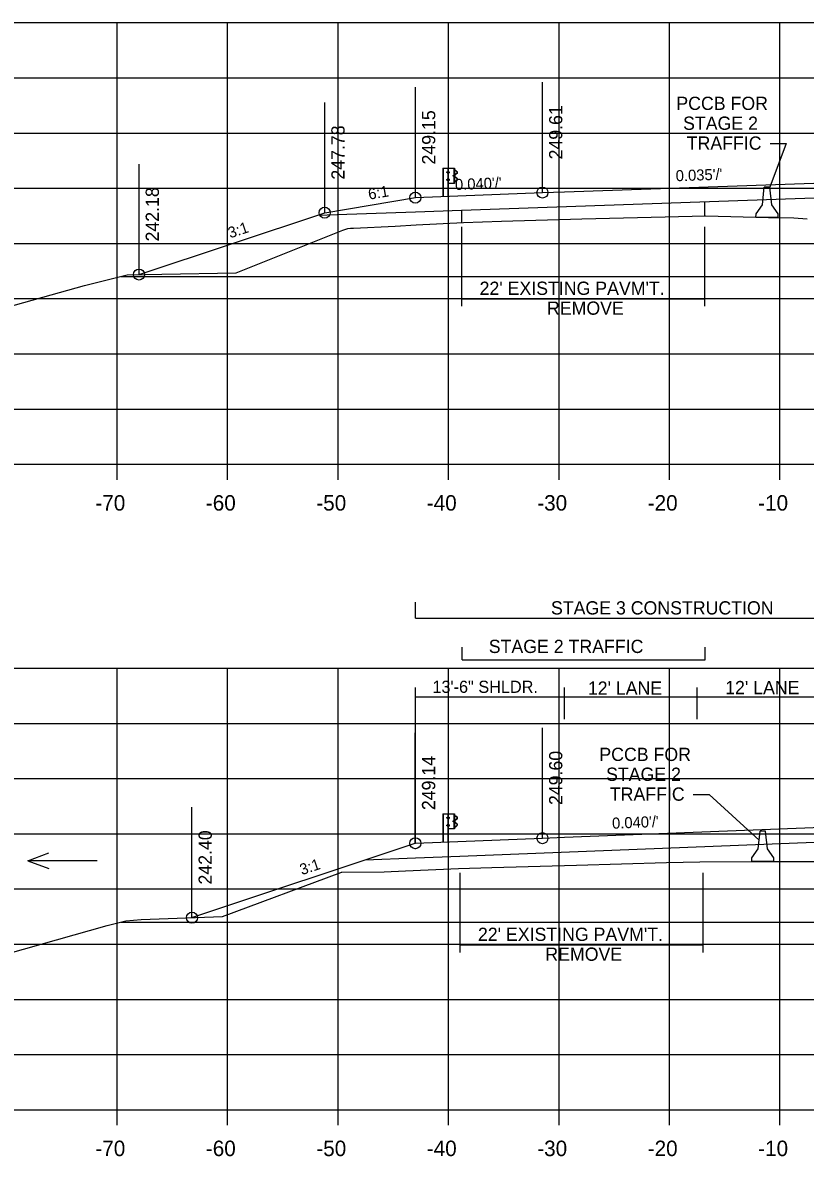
# Model space of a CAD drawing. Extents: x 1342547 to 1344156, y -1532351 to -1517216.
# Drawn here: x 1342624.3 to 1342695.2, y -1528712.1 to -1528609.4 of the extents above; entities that cross this region are included whole.
import ezdxf

# ---------------------------------------------------------------- set-up
doc = ezdxf.new("R2010")
doc.units = 0
for name, color, linetype in [('R_Alt Surface', 7, 'Continuous'), ('R_Axis', 7, 'Continuous'), ('R_Axis Annot', 7, 'Continuous'), ('R_Draft', 7, 'Continuous'), ('R_Exist Surface', 7, 'Continuous'), ('R_Fin Surface', 7, 'Continuous'), ('R_Grid', 7, 'Continuous'), ('R_MOT', 7, 'Continuous'), ('R_No Plot', 7, 'Continuous'), ('R_Water', 7, 'Continuous'), ('R_Xsect Elev', 7, 'Continuous'), ('R_Xsect Slope', 7, 'Continuous')]:
    doc.layers.add(name, color=color, linetype=linetype)

msp = doc.modelspace()

# ---------------------------------------------------------------- linework, layer by layer
at = {"layer": 'R_Alt Surface'}
for points in [[(1342664.04, -1528626.38), (1342702.87, -1528625.03)], [(1342651.02, -1528626.83), (1342659.87, -1528626.53)], [(1342659.87, -1528626.53), (1342664.04, -1528626.38)], [(1342663.89, -1528684.9), (1342702.87, -1528683.35)], [(1342655.33, -1528685.24), (1342659.87, -1528685.06)], [(1342659.87, -1528685.06), (1342663.89, -1528684.9)]]:
    msp.add_lwpolyline(points, dxfattribs=at)
at = {"layer": 'R_Axis'}
for p, q in [((1342562.87, -1528649.4), (1342842.87, -1528649.4)), ((1342632.87, -1528650.8), (1342632.87, -1528649.4)), ((1342642.87, -1528650.8), (1342642.87, -1528649.4)), ((1342652.87, -1528650.8), (1342652.87, -1528649.4)), ((1342662.87, -1528650.8), (1342662.87, -1528649.4)), ((1342672.87, -1528650.8), (1342672.87, -1528649.4)), ((1342682.87, -1528650.8), (1342682.87, -1528649.4)), ((1342692.87, -1528650.8), (1342692.87, -1528649.4)), ((1342562.87, -1528707.87), (1342842.87, -1528707.87)), ((1342632.87, -1528709.27), (1342632.87, -1528707.87)), ((1342642.87, -1528709.27), (1342642.87, -1528707.87)), ((1342652.87, -1528709.27), (1342652.87, -1528707.87)), ((1342662.87, -1528709.27), (1342662.87, -1528707.87)), ((1342672.87, -1528709.27), (1342672.87, -1528707.87)), ((1342682.87, -1528709.27), (1342682.87, -1528707.87)), ((1342692.87, -1528709.27), (1342692.87, -1528707.87))]:
    msp.add_line(p, q, dxfattribs=at)
at = {"layer": 'R_Draft'}
for p, q in [((1342662.35, -1528622.59), (1342662.35, -1528625.11)), ((1342662.38, -1528622.59), (1342662.38, -1528625.11)), ((1342662.75, -1528623), (1342662.75, -1528622.91)), ((1342662.81, -1528622.89), (1342662.76, -1528622.89)), ((1342662.81, -1528622.92), (1342662.76, -1528622.92)), ((1342662.81, -1528622.98), (1342662.76, -1528622.98)), ((1342662.81, -1528622.98), (1342662.76, -1528622.98)), ((1342662.81, -1528623.02), (1342662.76, -1528623.02)), ((1342662.88, -1528622.59), (1342662.81, -1528622.59)), ((1342662.81, -1528623.02), (1342662.81, -1528622.89)), ((1342662.84, -1528625.11), (1342662.84, -1528622.59)), ((1342662.88, -1528622.59), (1342662.87, -1528622.59)), ((1342662.93, -1528622.96), (1342662.87, -1528622.96)), ((1342662.88, -1528622.9), (1342662.93, -1528622.9)), ((1342662.88, -1528623.02), (1342662.93, -1528623.02)), ((1342662.93, -1528622.9), (1342662.93, -1528623.02)), ((1342663.37, -1528623.96), (1342663.37, -1528622.6)), ((1342663.52, -1528622.8), (1342663.41, -1528622.74)), ((1342663.51, -1528622.82), (1342663.41, -1528622.77)), ((1342663.46, -1528623.14), (1342663.63, -1528623.03)), ((1342663.47, -1528623.16), (1342663.65, -1528623.05)), ((1342663.64, -1528622.92), (1342663.51, -1528622.82)), ((1342663.65, -1528622.91), (1342663.52, -1528622.8)), ((1342662.74, -1528623.69), (1342662.74, -1528623.59)), ((1342662.8, -1528623.58), (1342662.75, -1528623.58)), ((1342662.8, -1528623.61), (1342662.75, -1528623.61)), ((1342662.8, -1528623.67), (1342662.75, -1528623.67)), ((1342662.8, -1528623.67), (1342662.75, -1528623.67)), ((1342662.8, -1528623.7), (1342662.75, -1528623.7)), ((1342662.8, -1528623.7), (1342662.8, -1528623.58)), ((1342662.87, -1528623.96), (1342662.84, -1528623.96)), ((1342662.93, -1528623.64), (1342662.87, -1528623.64)), ((1342662.93, -1528623.58), (1342662.88, -1528623.58)), ((1342662.93, -1528623.7), (1342662.88, -1528623.7)), ((1342662.93, -1528623.7), (1342662.93, -1528623.58)), ((1342663.36, -1528623.21), (1342663.31, -1528623.21)), ((1342663.31, -1528623.32), (1342663.31, -1528623.23)), ((1342663.36, -1528623.24), (1342663.31, -1528623.24)), ((1342663.36, -1528623.31), (1342663.31, -1528623.31)), ((1342663.36, -1528623.34), (1342663.31, -1528623.34)), ((1342663.36, -1528623.31), (1342663.32, -1528623.31)), ((1342663.36, -1528623.34), (1342663.36, -1528623.21)), ((1342663.4, -1528623.79), (1342663.51, -1528623.74)), ((1342663.41, -1528623.34), (1342663.42, -1528623.2)), ((1342663.41, -1528623.81), (1342663.52, -1528623.75)), ((1342663.44, -1528623.34), (1342663.44, -1528623.2)), ((1342663.61, -1528623.51), (1342663.46, -1528623.41)), ((1342663.62, -1528623.49), (1342663.47, -1528623.39)), ((1342663.51, -1528623.74), (1342663.64, -1528623.63)), ((1342663.52, -1528623.75), (1342663.65, -1528623.65)), ((1342686.04, -1528625.62), (1342686.04, -1528626.91)), ((1342664.04, -1528626.38), (1342664.04, -1528627.49)), ((1342664.04, -1528627.9), (1342664.04, -1528635.09)), ((1342686.05, -1528627.9), (1342686.05, -1528635.09)), ((1342664.04, -1528634.42), (1342686.05, -1528634.42)), ((1342659.87, -1528663.33), (1342659.87, -1528661.9)), ((1342659.87, -1528663.33), (1342702.78, -1528663.33)), ((1342664.11, -1528667.13), (1342664.11, -1528665.98)), ((1342686.11, -1528667.13), (1342686.11, -1528665.98)), ((1342664.11, -1528667.13), (1342686.11, -1528667.13)), ((1342662.35, -1528681.06), (1342662.35, -1528683.58)), ((1342662.38, -1528681.06), (1342662.38, -1528683.58)), ((1342662.75, -1528681.47), (1342662.75, -1528681.38)), ((1342662.81, -1528681.36), (1342662.76, -1528681.36)), ((1342662.81, -1528681.39), (1342662.76, -1528681.39)), ((1342662.81, -1528681.46), (1342662.76, -1528681.46)), ((1342662.81, -1528681.46), (1342662.76, -1528681.46)), ((1342662.81, -1528681.49), (1342662.76, -1528681.49)), ((1342662.88, -1528681.06), (1342662.81, -1528681.06)), ((1342662.81, -1528681.49), (1342662.81, -1528681.36)), ((1342662.84, -1528683.58), (1342662.84, -1528681.06)), ((1342662.88, -1528681.06), (1342662.87, -1528681.06)), ((1342662.93, -1528681.43), (1342662.87, -1528681.43)), ((1342662.88, -1528681.37), (1342662.93, -1528681.37)), ((1342662.88, -1528681.49), (1342662.93, -1528681.49)), ((1342662.93, -1528681.37), (1342662.93, -1528681.49)), ((1342663.36, -1528681.68), (1342663.31, -1528681.68)), ((1342663.36, -1528681.81), (1342663.36, -1528681.68)), ((1342663.37, -1528682.43), (1342663.37, -1528681.07)), ((1342663.52, -1528681.27), (1342663.41, -1528681.21)), ((1342663.51, -1528681.29), (1342663.41, -1528681.24)), ((1342663.41, -1528681.81), (1342663.42, -1528681.68)), ((1342663.44, -1528681.81), (1342663.44, -1528681.68)), ((1342663.46, -1528681.61), (1342663.63, -1528681.5)), ((1342663.47, -1528681.63), (1342663.65, -1528681.52)), ((1342663.64, -1528681.39), (1342663.51, -1528681.29)), ((1342663.65, -1528681.38), (1342663.52, -1528681.27)), ((1342662.74, -1528682.16), (1342662.74, -1528682.07)), ((1342662.8, -1528682.05), (1342662.75, -1528682.05)), ((1342662.8, -1528682.08), (1342662.75, -1528682.08)), ((1342662.8, -1528682.15), (1342662.75, -1528682.15)), ((1342662.8, -1528682.15), (1342662.75, -1528682.15)), ((1342662.8, -1528682.18), (1342662.75, -1528682.18)), ((1342662.8, -1528682.18), (1342662.8, -1528682.05)), ((1342662.87, -1528682.43), (1342662.84, -1528682.43)), ((1342662.93, -1528682.11), (1342662.87, -1528682.11)), ((1342662.93, -1528682.05), (1342662.88, -1528682.05)), ((1342662.93, -1528682.18), (1342662.88, -1528682.18)), ((1342662.93, -1528682.18), (1342662.93, -1528682.05)), ((1342663.31, -1528681.79), (1342663.31, -1528681.7)), ((1342663.36, -1528681.71), (1342663.31, -1528681.71)), ((1342663.36, -1528681.78), (1342663.31, -1528681.78)), ((1342663.36, -1528681.81), (1342663.31, -1528681.81)), ((1342663.36, -1528681.78), (1342663.32, -1528681.78)), ((1342663.4, -1528682.26), (1342663.51, -1528682.21)), ((1342663.41, -1528682.28), (1342663.52, -1528682.23)), ((1342663.61, -1528681.98), (1342663.46, -1528681.88)), ((1342663.62, -1528681.96), (1342663.47, -1528681.86)), ((1342663.51, -1528682.21), (1342663.64, -1528682.1)), ((1342663.52, -1528682.23), (1342663.65, -1528682.12)), ((1342663.89, -1528686.42), (1342663.89, -1528693.62)), ((1342685.89, -1528686.42), (1342685.89, -1528693.62)), ((1342663.89, -1528692.94), (1342685.89, -1528692.94))]:
    msp.add_line(p, q, dxfattribs=at)
for points in [[(1342693.42, -1528620.34), (1342691.95, -1528624.31)], [(1342691.97, -1528620.34), (1342693.42, -1528620.34)], [(1342662.35, -1528622.59), (1342662.81, -1528622.59), (1342662.8, -1528625.11)], [(1342685.01, -1528679.31), (1342686.45, -1528679.31)], [(1342686.45, -1528679.31), (1342690.99, -1528683.44)], [(1342662.35, -1528681.06), (1342662.81, -1528681.06), (1342662.8, -1528683.58)]]:
    msp.add_lwpolyline(points, dxfattribs=at)
for points in [[(1342662.75, -1528622.92), (1342662.75, -1528622.98), (1342662.72, -1528622.98), (1342662.72, -1528622.92)], [(1342662.8, -1528622.87), (1342662.8, -1528623.04), (1342662.81, -1528623.04), (1342662.81, -1528622.87)], [(1342663.4, -1528622.59), (1342663.4, -1528623.96), (1342662.87, -1528623.96), (1342662.88, -1528622.59)], [(1342662.93, -1528622.9), (1342662.93, -1528623.02), (1342662.88, -1528623.02), (1342662.88, -1528622.9)], [(1342662.74, -1528623.61), (1342662.74, -1528623.67), (1342662.71, -1528623.67), (1342662.71, -1528623.61)], [(1342662.79, -1528623.56), (1342662.79, -1528623.73), (1342662.8, -1528623.73), (1342662.8, -1528623.56)], [(1342662.93, -1528623.58), (1342662.93, -1528623.7), (1342662.88, -1528623.7), (1342662.88, -1528623.58)], [(1342663.3, -1528623.24), (1342663.3, -1528623.31), (1342663.28, -1528623.31), (1342663.28, -1528623.24)], [(1342663.36, -1528623.19), (1342663.36, -1528623.36), (1342663.37, -1528623.36), (1342663.37, -1528623.19)], [(1342662.75, -1528681.39), (1342662.75, -1528681.45), (1342662.72, -1528681.45), (1342662.72, -1528681.39)], [(1342662.8, -1528681.34), (1342662.8, -1528681.51), (1342662.81, -1528681.51), (1342662.81, -1528681.34)], [(1342663.4, -1528681.06), (1342663.4, -1528682.43), (1342662.87, -1528682.43), (1342662.88, -1528681.06)], [(1342662.93, -1528681.37), (1342662.93, -1528681.49), (1342662.88, -1528681.49), (1342662.88, -1528681.37)], [(1342663.36, -1528681.66), (1342663.36, -1528681.83), (1342663.37, -1528681.83), (1342663.37, -1528681.66)], [(1342662.74, -1528682.08), (1342662.74, -1528682.14), (1342662.71, -1528682.14), (1342662.71, -1528682.08)], [(1342662.79, -1528682.03), (1342662.79, -1528682.2), (1342662.8, -1528682.2), (1342662.8, -1528682.03)], [(1342662.93, -1528682.05), (1342662.93, -1528682.18), (1342662.88, -1528682.18), (1342662.88, -1528682.05)], [(1342663.3, -1528681.71), (1342663.3, -1528681.78), (1342663.28, -1528681.78), (1342663.28, -1528681.71)]]:
    msp.add_lwpolyline(points, close=True, dxfattribs=at)
for centre, radius, start, end in [((1342662.77, -1528622.91), 0.022, 134.5745, 222.2244), ((1342662.84, -1528622.95), 0.0922, 159.7423, 200.2577), ((1342662.78, -1528623), 0.025, 140.9334, 216.6234), ((1342663.5, -1528623.21), 0.0865, 118.106, 175.0444), ((1342663.5, -1528623.21), 0.0622, 118.106, 175.0444), ((1342663.6, -1528622.98), 0.062, 299.2499, 57.9783), ((1342663.6, -1528622.98), 0.0856, 299.2499, 57.9783), ((1342662.76, -1528623.6), 0.022, 134.5745, 222.2244), ((1342662.83, -1528623.64), 0.0922, 159.7423, 200.2577), ((1342662.77, -1528623.69), 0.025, 140.9334, 216.6234), ((1342663.33, -1528623.23), 0.022, 134.5745, 222.2244), ((1342663.4, -1528623.27), 0.0922, 159.7423, 200.2577), ((1342663.33, -1528623.32), 0.025, 140.9334, 216.6234), ((1342663.48, -1528623.35), 0.0703, 171.7804, 246.8536), ((1342663.43, -1528623.28), 0.0453, 282.9554, 86.0697), ((1342663.48, -1528623.35), 0.0462, 171.7804, 246.8536), ((1342663.57, -1528623.58), 0.0854, 325.2184, 59.12), ((1342663.57, -1528623.58), 0.109, 325.2184, 59.12), ((1342662.77, -1528681.38), 0.022, 134.5745, 222.2244), ((1342662.84, -1528681.42), 0.0922, 159.7423, 200.2577), ((1342662.78, -1528681.47), 0.025, 140.9334, 216.6234), ((1342663.33, -1528681.7), 0.022, 134.5745, 222.2244), ((1342663.5, -1528681.68), 0.0865, 118.106, 175.0444), ((1342663.5, -1528681.68), 0.0622, 118.106, 175.0444), ((1342663.6, -1528681.45), 0.062, 299.2499, 57.9783), ((1342663.6, -1528681.45), 0.0856, 299.2499, 57.9783), ((1342662.76, -1528682.07), 0.022, 134.5745, 222.2244), ((1342662.83, -1528682.11), 0.0922, 159.7423, 200.2577), ((1342662.77, -1528682.16), 0.025, 140.9334, 216.6234), ((1342663.4, -1528681.75), 0.0922, 159.7423, 200.2577), ((1342663.33, -1528681.79), 0.025, 140.9334, 216.6234), ((1342663.48, -1528681.82), 0.0703, 171.7804, 246.8536), ((1342663.43, -1528681.75), 0.0453, 282.9554, 86.0697), ((1342663.48, -1528681.82), 0.0462, 171.7804, 246.8536), ((1342663.57, -1528682.05), 0.0854, 325.2184, 59.12), ((1342663.57, -1528682.05), 0.109, 325.2184, 59.12)]:
    msp.add_arc(centre, radius, start, end, dxfattribs=at)
at = {"layer": 'R_Exist Surface'}
for points in [[(1342621.38, -1528635.59), (1342629.91, -1528633.22), (1342633.79, -1528632.24), (1342636.91, -1528632.19), (1342643.65, -1528632.06), (1342653.3, -1528628.21), (1342653.75, -1528628.04), (1342653.98, -1528628.03), (1342654.27, -1528628.02), (1342658.03, -1528627.83), (1342659.94, -1528627.73), (1342664.23, -1528627.49), (1342667.66, -1528627.39), (1342674.92, -1528627.17), (1342682.49, -1528627), (1342686.12, -1528626.91), (1342691.84, -1528627.05), (1342694.13, -1528627.09), (1342695.33, -1528627.17)], [(1342621.37, -1528694.18), (1342631.97, -1528691.17), (1342633.67, -1528690.76), (1342635.04, -1528690.65), (1342642.4, -1528690.36), (1342653.11, -1528686.37), (1342653.17, -1528686.35), (1342653.22, -1528686.35), (1342657.04, -1528686.33), (1342658.97, -1528686.24), (1342663.77, -1528686.01), (1342666.8, -1528685.93), (1342674.46, -1528685.71), (1342682.59, -1528685.49), (1342685.63, -1528685.41), (1342691.54, -1528685.4), (1342693.5, -1528685.38), (1342696.44, -1528685.39)]]:
    msp.add_lwpolyline(points, dxfattribs=at)
at = {"layer": 'R_Fin Surface'}
for p, q in [((1342633.22, -1528632.4), (1342703.87, -1528632.4)), ((1342633.22, -1528690.87), (1342703.87, -1528690.87))]:
    msp.add_line(p, q, dxfattribs=at)
for points in [[(1342634.85, -1528632.22), (1342651.66, -1528626.62), (1342659.87, -1528625.25), (1342671.37, -1528624.79), (1342673.37, -1528624.72), (1342702.87, -1528623.7), (1342734.37, -1528622.61)], [(1342639.64, -1528690.47), (1342659.86, -1528683.73), (1342659.87, -1528683.73), (1342671.37, -1528683.27), (1342673.37, -1528683.19), (1342702.87, -1528682.02), (1342732.37, -1528680.84), (1342734.37, -1528680.76), (1342745.87, -1528680.31), (1342754.07, -1528681.67), (1342792.91, -1528694.62)]]:
    msp.add_lwpolyline(points, dxfattribs=at)
at = {"layer": 'R_Grid'}
for p, q in [((1342562.87, -1528609.4), (1342842.87, -1528609.4)), ((1342632.87, -1528649.4), (1342632.87, -1528609.4)), ((1342642.87, -1528649.4), (1342642.87, -1528609.4)), ((1342652.87, -1528649.4), (1342652.87, -1528609.4)), ((1342662.87, -1528649.4), (1342662.87, -1528609.4)), ((1342672.87, -1528649.4), (1342672.87, -1528609.4)), ((1342682.87, -1528649.4), (1342682.87, -1528609.4)), ((1342692.87, -1528649.4), (1342692.87, -1528609.4)), ((1342562.87, -1528614.4), (1342842.87, -1528614.4)), ((1342562.87, -1528619.4), (1342842.87, -1528619.4)), ((1342562.87, -1528624.4), (1342842.87, -1528624.4)), ((1342562.87, -1528629.4), (1342842.87, -1528629.4)), ((1342562.87, -1528634.4), (1342842.87, -1528634.4)), ((1342562.87, -1528639.4), (1342842.87, -1528639.4)), ((1342562.87, -1528644.4), (1342842.87, -1528644.4)), ((1342562.87, -1528649.4), (1342842.87, -1528649.4)), ((1342562.87, -1528667.87), (1342842.87, -1528667.87)), ((1342632.87, -1528707.87), (1342632.87, -1528667.87)), ((1342642.87, -1528707.87), (1342642.87, -1528667.87)), ((1342652.87, -1528707.87), (1342652.87, -1528667.87)), ((1342662.87, -1528707.87), (1342662.87, -1528667.87)), ((1342672.87, -1528707.87), (1342672.87, -1528667.87)), ((1342682.87, -1528707.87), (1342682.87, -1528667.87)), ((1342692.87, -1528707.87), (1342692.87, -1528667.87)), ((1342562.87, -1528672.87), (1342842.87, -1528672.87)), ((1342562.87, -1528677.87), (1342842.87, -1528677.87)), ((1342562.87, -1528682.87), (1342842.87, -1528682.87)), ((1342562.87, -1528687.87), (1342842.87, -1528687.87)), ((1342562.87, -1528692.87), (1342842.87, -1528692.87)), ((1342562.87, -1528697.87), (1342842.87, -1528697.87)), ((1342562.87, -1528702.87), (1342842.87, -1528702.87)), ((1342562.87, -1528707.87), (1342842.87, -1528707.87))]:
    msp.add_line(p, q, dxfattribs=at)
at = {"layer": 'R_MOT'}
for p, q in [((1342691.28, -1528625.89), (1342691.45, -1528624.31)), ((1342691.7, -1528624.31), (1342691.45, -1528624.31)), ((1342691.95, -1528624.31), (1342691.7, -1528624.31)), ((1342692.12, -1528625.89), (1342691.95, -1528624.31)), ((1342690.71, -1528626.72), (1342691.28, -1528625.89)), ((1342692.71, -1528626.72), (1342692.12, -1528625.89)), ((1342690.7, -1528627.06), (1342690.71, -1528626.72)), ((1342692.7, -1528627.06), (1342690.7, -1528627.06)), ((1342692.7, -1528627.06), (1342692.71, -1528626.72)), ((1342690.91, -1528684.23), (1342691.07, -1528682.65)), ((1342691.32, -1528682.65), (1342691.07, -1528682.65)), ((1342691.57, -1528682.65), (1342691.32, -1528682.65)), ((1342691.74, -1528684.23), (1342691.57, -1528682.65)), ((1342690.33, -1528685.06), (1342690.91, -1528684.23)), ((1342692.33, -1528685.06), (1342691.74, -1528684.23)), ((1342690.32, -1528685.4), (1342690.33, -1528685.06)), ((1342692.32, -1528685.4), (1342690.32, -1528685.4)), ((1342692.32, -1528685.4), (1342692.33, -1528685.06))]:
    msp.add_line(p, q, dxfattribs=at)
at = {"layer": 'R_No Plot'}
for centre in [(1342659.87, -1528625.25), (1342671.37, -1528624.79), (1342651.66, -1528626.62), (1342634.85, -1528632.22), (1342659.86, -1528683.73), (1342659.87, -1528683.73), (1342671.37, -1528683.27), (1342639.64, -1528690.47)]:
    msp.add_circle(centre, 0.5, dxfattribs=at)
at = {"layer": 'R_Water'}
for p, q in [((1342624.77, -1528685.31), (1342626.69, -1528684.61)), ((1342631.05, -1528685.31), (1342624.77, -1528685.31)), ((1342624.77, -1528685.31), (1342626.69, -1528686.01))]:
    msp.add_line(p, q, dxfattribs=at)
at = {"layer": 'R_Xsect Elev'}
for p, q in [((1342671.37, -1528624.79), (1342671.37, -1528614.79)), ((1342659.87, -1528625.25), (1342659.87, -1528615.25)), ((1342651.66, -1528626.62), (1342651.66, -1528616.62)), ((1342634.85, -1528632.22), (1342634.85, -1528622.22)), ((1342659.87, -1528682.89), (1342659.87, -1528669.63)), ((1342673.37, -1528672.5), (1342673.37, -1528669.63)), ((1342685.37, -1528672.5), (1342685.37, -1528669.63)), ((1342745.87, -1528670.49), (1342659.87, -1528670.49)), ((1342671.37, -1528683.27), (1342671.37, -1528673.27)), ((1342659.86, -1528683.73), (1342659.86, -1528673.73)), ((1342659.86, -1528683.73), (1342659.86, -1528673.73)), ((1342659.87, -1528683.73), (1342659.87, -1528673.73)), ((1342659.87, -1528683.73), (1342659.87, -1528673.73)), ((1342639.64, -1528690.47), (1342639.64, -1528680.47))]:
    msp.add_line(p, q, dxfattribs=at)

# ---------------------------------------------------------------- texts
at = {"layer": 'R_Axis Annot'}
for s, p in [('-70', (1342630.9, -1528653.6)), ('-60', (1342640.9, -1528653.6)), ('-50', (1342650.9, -1528653.6)), ('-40', (1342660.9, -1528653.6)), ('-30', (1342670.9, -1528653.6)), ('-20', (1342680.9, -1528653.6)), ('-10', (1342690.9, -1528653.6)), ('-70', (1342630.9, -1528712.07)), ('-60', (1342640.9, -1528712.07)), ('-50', (1342650.9, -1528712.07)), ('-40', (1342660.9, -1528712.07)), ('-30', (1342670.9, -1528712.07)), ('-20', (1342680.9, -1528712.07)), ('-10', (1342690.9, -1528712.07))]:
    msp.add_text(s, height=1.4, dxfattribs=at).set_placement(p)
at = {"layer": 'R_Draft'}
for s, p in [('PCCB FOR', (1342683.49, -1528617.31)), ('STAGE 2', (1342684.1, -1528619.11)), ('TRAFFIC', (1342684.43, -1528620.91)), ("22' EXISTING PAVM'T.", (1342665.68, -1528634.06)), ('REMOVE', (1342671.78, -1528635.86)), ('STAGE 3 CONSTRUCTION', (1342672.14, -1528663.01)), ('STAGE 2 TRAFFIC', (1342666.51, -1528666.5)), ('PCCB FOR', (1342676.52, -1528676.28)), ('STAGE 2', (1342677.13, -1528678.08)), ('TRAFFIC', (1342677.47, -1528679.88)), ("22' EXISTING PAVM'T.", (1342665.53, -1528692.58)), ('REMOVE', (1342671.63, -1528694.38))]:
    msp.add_text(s, height=1.2, dxfattribs=at).set_placement(p)
at = {"layer": 'R_Xsect Elev'}
for s, p in [('249.61', (1342673.17, -1528621.79)), ('249.15', (1342661.67, -1528622.25)), ('247.78', (1342653.46, -1528623.62)), ('242.18', (1342636.65, -1528629.22)), ('249.60', (1342673.17, -1528680.27)), ('249.14', (1342661.66, -1528680.73)), ('249.14', (1342661.67, -1528680.73)), ('242.40', (1342641.44, -1528687.47))]:
    msp.add_text(s, height=1.2, rotation=90, dxfattribs=at).set_placement(p)
for s, height, p in [('13\'-6" SHLDR.', 1.1, (1342661.41, -1528670.11)), ("12' LANE", 1.2, (1342675.48, -1528670.28)), ("12' LANE", 1.2, (1342687.91, -1528670.23))]:
    msp.add_text(s, height=height, dxfattribs=at).set_placement(p)
at = {"layer": 'R_Xsect Slope'}
for s, rotation, p in [("0.035'/'", 1.9875, (1342683.45, -1528623.77)), ("0.040'/'", 2.2906, (1342663.47, -1528624.57)), ('6:1', 9.4623, (1342655.68, -1528625.44)), ('3:1', 18.4349, (1342643.1, -1528628.95)), ("0.040'/'", 2.282, (1342677.69, -1528682.42)), ('3:1', 18.4349, (1342649.59, -1528686.63))]:
    msp.add_text(s, height=1, rotation=rotation, dxfattribs=at).set_placement(p)

doc.saveas('drawing.dxf')
